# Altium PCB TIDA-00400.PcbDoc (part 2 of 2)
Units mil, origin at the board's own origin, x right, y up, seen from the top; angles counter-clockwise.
Board outline 2000 x 2000 mil, 2 copper layers (Top Layer, Bottom Layer), stack 62 mil thick; 123 components, 39 nets, 250 pads, 73 vias.
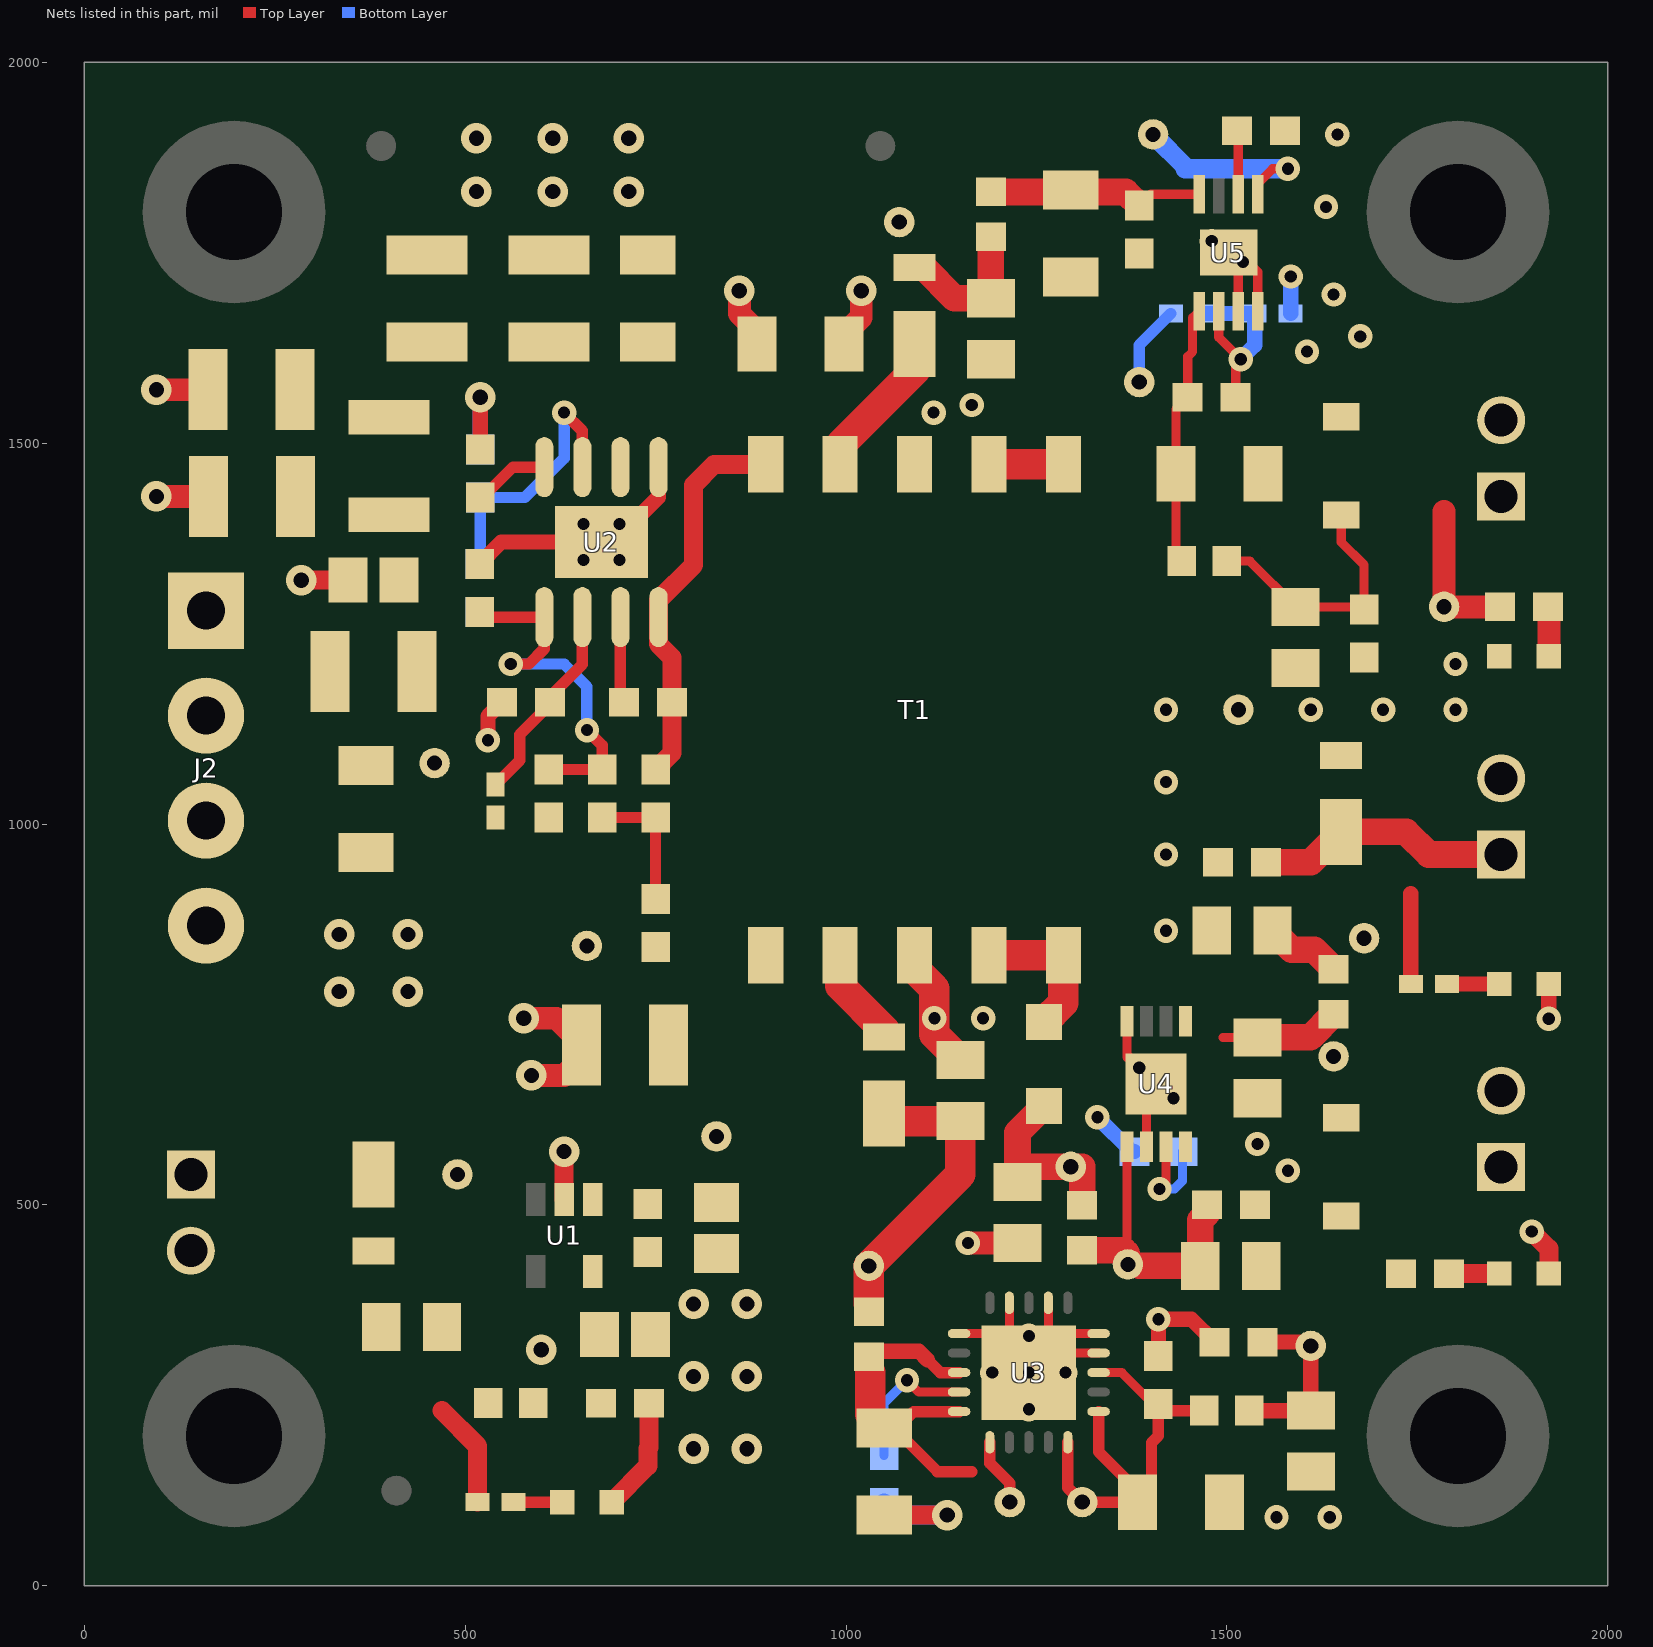
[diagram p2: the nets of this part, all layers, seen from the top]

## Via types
v1: diameter 32, hole 16, Top Layer to Bottom Layer, tented both sides, 48 vias
v2: diameter 40, hole 20, Top Layer to Bottom Layer, tented both sides, 25 vias

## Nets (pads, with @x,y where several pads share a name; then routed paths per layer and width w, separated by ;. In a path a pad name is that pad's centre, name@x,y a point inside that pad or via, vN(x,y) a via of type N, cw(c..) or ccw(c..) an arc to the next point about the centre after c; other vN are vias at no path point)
9.3V_NON_ISO: C8.1 C14.1 C15.2 C16.1 D2.2 R4.2 T1.10 TP5.1 TP6.1 U1.1
+3.3V_NON_ISO: C4.2 D1.1 J1.1 L2.2 R2.1 TP2.1 | length 139.2
  Top Layer w25: 470,230 516.38,183.62 R2.1@516.38,110
+5V_ISO: C30.1 C32.2 D9.1 J4.1 L8.2 R7.1 TP18.1 | length 556.9
  Top Layer w20: R7.1@1741.38,790 1741.38,908.62
  Top Layer w35: C32.2@1551.5,950 1610.2,950 D9.1@1650,989.8 1735.2,989.8 1765,960 J4.1@1860,960 ; C30.1@1560,860 1585,835 1614.53,835 L8.2@1640,809.53
+6V_ISO: C28.1 C29.2 L5.2 TP12.1 U4.5 U4.8 | length 387
  Top Layer w12: U4.5@1368.7,576.3 1368.7,436.3 TP12.1@1385,420
  Top Layer w35: L5.2@1310,440.47 1364.53,440.47 TP12.1@1368.7,436.3 ; TP12.1@1385,420 C28.1@1465,420 1465,480 1473.5,488.5 C29.2@1473.5,500
+15V_ISO: C31.2 C36.1 D8.1 J5.1 L7.2 R6.1 TP16.1 | length 225.2
  Top Layer w20: L7.2@1529.53,230 C36.1@1610,230 1610,305 1595,320 C31.2@1546.5,320
+18V_ISO: C18.1 L3.2 TP9.1 U3.13 U3.15 U3.16 | length 536.8
  Top Layer w15: C18.1@1050,207.09 C18.1@1062.91,207.09 ; 1106.97,296.77 1123.74,280 U3.13@1148.46,280 ; U3.15@1148.46,228.82 1088.82,228.82 1067.09,207.09 C18.1@1062.91,207.09 ; 1165,150 1120,150 C18.1@1062.91,207.09 ; U3.16@1188.82,188.46 1188.82,161.18 1215,135 TP9.1@1215,110
  Top Layer w20: L3.2@1030,300.47 1037.53,308 1095.74,308 1106.97,296.77
  Top Layer w40: 1032,280.7 1032,225.09 C18.1@1050,207.09
+24VDC: C2.1 C3.1 F1.1 L1.1 RV1.2 TP1.1
-15V_ISO: C35.2 C37.2 D7.2 J3.1 L6.2 R8.1 TP19.1 | length 536.8
  Top Layer w12: L6.2@1499.53,1345 1530,1345 C35.2@1590,1285 C37.2@1676.5,1285 ; D7.2@1650,1405.53 1650,1370 1680,1340 C37.2@1680,1281.5
  Top Layer w30: 1785,1410 TP19.1@1785,1285 R8.1@1858.5,1285
-18V_ISO: C22.1 C24.2 L4.2 TP14.1 U5.5 U5.8 | length 547.5
  Top Layer w12: C24.2@1385,1811.5 1400.1,1826.6 U5.8@1463.6,1826.6 ; U5.5@1540.4,1826.6 1540.4,1840.4 1560,1860 v1(1580,1860)
  Top Layer w35: L4.2@1190,1829.53 1366.97,1829.53 C24.2@1385,1811.5
  Bottom Layer w25: TP14.1@1403,1905 1448,1860 ; 1445,1860 1448,1860 ; v1(1580,1860) 1448,1860
GND: C1.2 C2.2 C3.2 C4.1 C5.1 C6.2 C7.1 C8.2 C9.2 C10.2 C13.1 C14.2 C16.2 C17.1 D1.2 D3.1 J1.2 J2.3 J2.4 R1.1 R12.1 RV1.1 U1.2 U2.1 U2.9 | length 998.9
  Top Layer w20: R1.1@518.98,1341.5 547.48,1370 U2.9@678.98,1370 695,1370 753.98,1428.98 U2.1@753.98,1468.43 ; v1(530,1110) 530,1141.5 C6.2@548.5,1160
  Top Layer w25: v2(285,1320) C3.2@346.54,1320 ; U1.2@630,507.24 v2(630,570) ; D3.1@692.48,110 740,157.52 740,180 ; 741.5,181.5 C10.2@741.5,240
  Top Layer w30: v2(95,1430) C2.2@163.23,1430 ; v2(95,1570) C1.2@162.91,1570 ; v2(577.09,745) 620,745 C8.2@640,725 ; v2(587.09,670) 630,670 C8.2@650,690 ; v2(860,1700) 860,1670 882.91,1647.09 C17.1@882.91,1630
  other v1: 655.35,1346.38 702.6,1346.38 655.35,1393.62 702.6,1393.62
  other v2: 800,180 870,180 800,275 870,275 800,370 870,370 335,780 425,780 335,855 425,855 515,1830 615,1830 715,1830 515,1900 615,1900 715,1900
NetC1_1: C1.1 C5.2 C7.2 C13.2 L1.2 R3.2 R11.2 TP3.1 U2.2 | length 117
  Top Layer w20: R3.2@520,1491.49 TP3.1@520,1550
  Bottom Layer w20: R11.2@520,1491.5 TP3.1@520,1550
NetC6_1: C6.1 D2.1 U2.6 | length 260.1
  Top Layer w15: D2.1@540,1051.65 571.8,1083.45 571.8,1117.33 611.5,1157.03 C6.1@611.5,1160 ; C6.1@611.5,1167.03 653.98,1209.51 U2.6@653.98,1271.57
NetC9_1: C9.1 C10.1 L2.1 TP4.1 U1.5
NetC11_1: C11.1 C15.1 R5.1 | length 177
  Top Layer w15: C11.1@680,1008.5 R5.1@750,1008.5 C15.1@750,901.5
NetC11_2: C11.2 R1.2 R4.1 U2.5 | length 480.9
  Top Layer w15: R1.2@518.98,1278.5 525.91,1271.57 U2.5@603.98,1271.57 603.98,1230 583.98,1210 v1(560,1210) ; R4.1@610,1071.5 C11.2@680,1071.5 680,1103.18 v1(660,1123.18)
  Bottom Layer w15: v1(560,1210) 630,1210 660,1180 v1(660,1123.18)
NetC12_1: C12.1 U2.7 | length 103.8
  Top Layer w15: C12.1@698.5,1170 703.98,1175.47 U2.7@703.98,1271.57
NetC12_2: C12.2 R5.2 T1.1 U2.8 | length 514.7
  Top Layer w25: R5.2@750,1071.5 771.5,1092.99 C12.2@771.5,1160 771.5,1218.5 753.98,1236.02 U2.8@753.98,1271.57 753.98,1293.98 800,1340 800,1445 827.05,1472.05 T1.1@894.72,1472.05
NetC19_1: C19.1 D4.1 L3.1 TP7.1 | length 393.8
  Top Layer w40: L3.1@1030,370 TP7.1@1030,420 1150,540 C19.1@1150,610 1059.8,610 D4.1@1050,619.8
NetC20_2: C20.2 D5.2 L4.1 TP8.1 | length 197.1
  Top Layer w35: D5.2@1090,1730.2 1102.19,1730.2 1142.39,1690 C20.2@1190,1690 L4.1@1190,1770.47
NetC21_1: C21.1 D6.1 L5.1 TP10.1 | length 258.1
  Top Layer w35: D6.1@1260,629.88 1225,594.88 C21.1@1225,530 1245,550 1310,550 L5.1@1310,499.53
NetC23_1: C23.1 C25.2 L7.1 TP11.1 U3.1 U3.3 U3.20 | length 598.6
  Top Layer w12: U3.3@1331.54,280 1362,280 1403.5,238.5 C25.2@1410,238.5
  Top Layer w15: U3.20@1291.18,188.46 1291.18,128.82 TP11.1@1310,110 C23.1@1382.91,110 ; U3.1@1331.54,228.82 1331.54,176.1 1382.91,124.72 C23.1@1382.91,110 ; L7.1@1470.47,230 1418.5,230 C25.2@1410,238.5 1410,197 1401,188 1401,128.09 C23.1@1382.91,110
NetC26_1: C26.1 C27.1 L6.1 R10.1 TP13.1 U5.1 | length 451
  Top Layer w12: L6.1@1440.47,1345 1432.91,1352.56 C26.1@1432.91,1460 1432.91,1544.41 C27.1@1448.5,1560 1448.5,1613.5 1455,1620 1455,1664.4 U5.1@1463.6,1673
  Bottom Layer w15: TP13.1@1385,1580 1385,1628.62 R10.1@1426.38,1670
NetC27_2: C27.2 R9.1 R10.2 U5.2 | length 258
  Top Layer w12: U5.2@1489.2,1673 1489.2,1638.79 v1(1517.99,1610) 1511.49,1603.51 C27.2@1511.49,1560
  Bottom Layer w20: R10.2@1473.62,1670 R9.1@1536.38,1670 1536.38,1628.39 v1(1517.99,1610)
NetC33_1: C33.1 U5.6 | length 80.1
  Top Layer w12: U5.6@1514.8,1826.6 C33.1@1514.8,1906.69
NetC34_1: C34.1 L8.1 TP17.1 U4.1 | length 157.6
  Top Layer w12: 1495,720 C34.1@1540,720
  Top Layer w35: C34.1@1540,720 1609.53,720 L8.1@1640,750.47
NetC38_1: C38.1 U4.7 | length 131.6
  Top Layer w12: v1(1411.52,521) 1419.9,529.38 U4.7@1419.9,576.3
  Bottom Layer w12: v1(1411.52,521) 1431,521 1441.5,531.5 C38.1@1441.5,570
NetC39_1: C39.1 U3.14 | length 185.9
  Top Layer w12: v1(1080,270) 1095.59,254.41 U3.14@1148.46,254.41
  Bottom Layer w12: C39.1@1050,171.5 1050,240 v1(1080,270)
NetD3_2: D3.2 R2.2 | length 63.9
  Top Layer w15: R2.2@563.62,110 D3.2@627.52,110
NetD4_2: D4.2 T1.9 | length 121.8
  Top Layer w40: T1.9@992.36,827.95 992.36,787.64 D4.2@1050,730
NetD5_1: D5.1 T1.2 | length 198.2
  Top Layer w40: T1.2@992.36,1472.05 992.36,1497.36 1090,1595 D5.1@1090,1629.8
NetD6_2: D6.2 T1.6 T1.7 | length 195.9
  Top Layer w40: T1.7@1187.64,827.95 T1.6@1285.28,827.95 1285.28,765.39 D6.2@1260,740.12
NetD10_1: D10.1 R8.2 | length 64
  Top Layer w30: D10.1@1922.48,1220 R8.2@1922.48,1284.02
NetD11_2: D11.2 R7.2 | length 68.9
  Top Layer w20: R7.2@1788.62,790 D11.2@1857.52,790
NetD12_2: D12.2 R6.2 | length 66
  Top Layer w25: R6.2@1791.5,410 D12.2@1857.52,410
NetF1_2: F1.2 J2.1 J2.2
NetR3_1: R3.1 U2.4 | length 100.5
  Top Layer w15: R3.1@520,1428.5 522.97,1428.5 562.89,1468.43 U2.4@603.98,1468.43
NetR11_1: R11.1 R12.2 U2.3 | length 358.8
  Top Layer w15: v1(630,1540) 653.98,1516.02 U2.3@653.98,1468.43
  Bottom Layer w15: R12.2@520,1342.52 R11.1@520,1428.5 578.5,1428.5 630,1480 v1(630,1540)
NetT1_4: T1.4 T1.5 | length 97.6
  Top Layer w40: T1.4@1187.64,1472.05 T1.5@1285.28,1472.05
SGND: C17.2 C18.2 C19.2 C20.1 C21.2 C22.2 C23.2 C24.1 C25.1 C26.2 C28.2 C29.1 C30.2 C31.1 C32.1 C33.2 C34.2 C35.1 C36.2 C37.1 C38.2 C39.2 D7.1 D8.2 D9.2 D10.2 D11.1 D12.1 J3.2 J4.2 J5.2 R9.2 T1.3 T1.8 TP15.1 U3.4 U3.5 U3.7 U3.9 U3.11 U3.21 U4.4 U4.6 U4.9 U5.3 U5.4 U5.9 | length 1470
  Top Layer w12: U3.11@1148.46,331.18 U3.21@1188.82,331.18 ; U3.21@1214.41,305.59 U3.9@1214.41,371.54 ; U3.7@1265.59,371.54 1265.59,305.59 U3.4@1331.54,305.59 ; U3.21@1291.18,331.18 U3.5@1331.54,331.18 ; U4.9@1368.8,693.8 U4.4@1368.8,741.3 ; U4.9@1370.5,695.5 U4.9@1407,659 1394.3,646.3 U4.6@1394.3,576.3 ; U5.9@1502.4,1750 U5.9@1514.8,1737.6 ; U5.3@1514.8,1673 U5.9@1514.8,1737.6 ; U5.4@1540.4,1673 1540.4,1724.6 1527.4,1737.6 U5.9@1514.8,1737.6
  Top Layer w20: C25.1@1410,301.5 v1(1410,350) 1453.5,350 C31.1@1483.5,320 ; v1(1922.48,744.48) D11.1@1922.48,790
  Top Layer w25: C18.2@1050,92.91 v2(1132.91,92.91) ; v1(1900,465) 1922.48,442.52 D12.1@1922.48,410
  Top Layer w30: C17.2@997.09,1630 997.09,1642.09 1020,1665 v2(1020,1700) ; v1(1160,450) C21.2@1225,450
  Top Layer w40: T1.8@1090,827.95 1090,810 1116,784 1116,724 C19.2@1150,690
  Bottom Layer w20: v1(1330,615) 1375,570 C38.2@1378.5,570 ; R9.2@1583.62,1670 v1(1583.62,1718.62)
  Bottom Layer w25: C39.2@1050,108.5 1065.59,92.91 v2(1132.91,92.91)
  other v1: 1565,90 1635,90 1240,231.84 1191.84,280 1240,280 1288.16,280 1240,328.16 1580,545 1540,580 1430,640 1385,680 1116,745 1180,745 1420,860 1420,960 1420,1055 1420,1150 1610,1150 1705,1150 1800,1150 1800,1210 1115,1540 1165,1550 1605,1620 1675,1640 1640,1695 1521.1,1737.6 1480,1765 1630,1810 1645,1905
pads on no net: FID1.1 FID2.1 FID3.1 FID4.1 FID5.1 FID6.1 H1.1 H2.1 H3.1 H4.1 U1.3 U1.4 U3.2 U3.6 U3.8 U3.10 U3.12 U3.17 U3.18 U3.19 U4.2 U4.3 U5.7

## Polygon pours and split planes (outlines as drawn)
SGND on Top Layer "Top Layer-No Net" (solid, remove dead copper, pour order 39): 1560,175 1645,175 1660,160 1660,80 1640,60 1555,60 1455,65 1445,75 1445,135 1475,165 1550,165
SGND on Top Layer "Top Layer-No Net" (solid, remove dead copper, pour order 45): 1570,1420 1500,1420 1495,1425 1495,1505 1505,1515 1560,1515 1580,1535 1580,1645 1570,1655 1515,1655 1510,1660 1510,1720 1505,1725 1390,1725 1325,1660 1325,1600 1310,1585 1160,1585 1160,1635 1250,1635 1260,1645 1260,1750 1275,1765 1435,1765 1450,1780 1580,1780 1610,1810 1610,1880 1600,1890 1560,1890 1555,1895 1555,1925 1560,1930 1695,1930 1700,1925 1700,1550
+15V_ISO on Top Layer "Top Layer-No Net" (solid, remove dead copper, pour order 43): 1515,255 1515,215 1525,205 1625,205 1650,230 1650,325 1690,365 1725,365 1735,375 1735,455 1755,475 1835,475 1865,505 1915,505 1930,520 1930,580 1920,590 1770,590 1710,530 1630,530 1600,500 1600,355 1585,340 1545,340 1535,330 1535,275
SGND on Top Layer "Top Layer-No Net" (solid, remove dead copper, pour order 35): 1570,385 1520,385 1520,605 1505,620 1355,620 1335,640 1335,750 1375,750 1375,700 1380,695 1450,695 1480,665 1570,665 1600,635 1680,635 1685,630 1685,605 1680,600 1610,600 1600,590 1600,540 1575,515 1575,390
NetC34_1 on Top Layer "Top Layer-No Net" (solid, remove dead copper, pour order 51): 1440,725 1475,725 1510,690 1600,690 1625,665 1670,665 1680,675 1680,765 1675,770 1440,770
-18V_ISO on Top Layer "Top Layer-No Net" (solid, remove dead copper, pour order 48): 1465,1810 1440,1810 1425,1795 1260,1795 1240,1815 1125,1815 1120,1820 1120,1885 1125,1890 1345,1890 1390,1935 1440,1935 1450,1925 1450,1865 1465,1850
9.3V_NON_ISO on Top Layer "Top Layer-No Net" (solid, remove dead copper, pour order 40): 640,480 880,480 890,490 890,760 910,780 910,860 690,860 640,910 640,1020 520,1020 500,1000 500,810 520,790 720,790 740,770 740,570 720,550 640,550
NetC9_1 on Top Layer "Top Layer-No Net" (solid, remove dead copper, pour order 44): 580,190 590,180 680,180 690,190 690,440 650,440 640,430 640.12,360 620,340 590,340 580,330
+24VDC on Top Layer "Top Layer-No Net" (solid, remove dead copper, pour order 34): 410,1140 380,1110 350,1110 340,1100 340,1050 350,1040 480,1040 490,1050 490,1210 470,1230 470,1420 460,1430 330,1430 310,1450 310,1480 300,1490 250,1490 250,1380 410,1380
NetF1_2 on Top Layer "Top Layer-No Net" (solid, remove dead copper, pour order 32): 340,1150 340,1250 290,1250 200,1340 90,1340 80,1330 80,1120 110,1090 210,1090 270,1150
NetC23_1 on Top Layer "Top Layer-No Net" (solid, remove dead copper, pour order 41): 1395,55 1410,70 1410,155 1450,195 1480,195 1485,200 1485,255 1380,255 1380,230 1365,215 1320,215 1320,195 1280,195 1280,75 1300,55
-15V_ISO on Top Layer "Top Layer-No Net" (solid, remove dead copper, pour order 50): 1495,1385 1610,1385 1620,1395 1620,1430 1660,1470 1910,1470 1910,1380 1905,1375 1720,1375 1710,1365 1710,1280 1705,1275 1495,1275 1485,1285 1485,1375
+18V_ISO on Top Layer "Top Layer-No Net" (solid, remove dead copper, pour order 37): 1200,140 1130,140 1090,180 1000,180 990,190 990,300 1000,310 1100,310 1116.52,292.75 1110,230 1140,230 1140,200 1150,190 1195,190 1195,145 1200,145
NetC20_2 on Top Layer "Top Layer-No Net" (solid, remove dead copper, pour order 52): 1230,1680 1135,1680 1100,1715 1030,1715 1020,1725 1020,1805 1035,1820 1080,1820 1120,1780 1225,1780 1230,1775 1230,1690
NetC26_1 on Top Layer "Top Layer-No Net" (solid, remove dead copper, pour order 49): 1460,1695 1460,1300 1450,1290 1390,1290 1375,1305 1375,1535 1345,1565 1345,1650 1390,1695
+5V_ISO on Top Layer "Top Layer-No Net" (solid, remove dead copper, pour order 47): 1685,795 1555,795 1540,810 1540,995 1575,1030 1730,1030 1765,995 1920,995 1930,985 1930,885 1925,880 1715,880 1705,870 1705,815
+6V_ISO on Top Layer "Top Layer-No Net" (solid, remove dead copper, pour order 53): 1280,460 1420,460 1460,500 1460,550 1450,560 1450,590 1480,590 1490,580 1490,400 1485,395 1360,395 1335,420 1280,420 1275,425 1275,455
NetC21_1 on Top Layer "Top Layer-No Net" (solid, remove dead copper, pour order 54): 1304,481 1275,510 1195,510 1195,540 1210,555 1210,630 1235,655 1290,655 1300,645 1300,605 1335,570 1335,481
NetC19_1 on Top Layer "Top Layer-No Net" (solid, remove dead copper, pour order 55): 1100,350 995,350 990,355 990,615 1010,635 1165,635 1165,545 1110,490 1110,360
GND on Top Layer "Top Layer-No Net" (solid, remove dead copper, pour order 56): 240,1055 310,985 455,985 470,970 470,755 450,735 95,735 80,750 80,1035 100,1055
GND on Top Layer "Top Layer-No Net" (solid, remove dead copper, pour order 57): 415,450 395,470 95,470 80,455 80,370 90,360 310,360 345,325 345,285 355,275 410,275 415,280
GND on Top Layer "Top Layer-No Net" (solid, remove dead copper, pour order 58): 880,450 895,435 895,85 880,70 700,70 685,85 685,120 730,165 730,400 720,410.02 720,440 730,450
+3.3V_NON_ISO on Top Layer "Top Layer-No Net" (solid, remove dead copper, pour order 46): 540,670 520,690 110,690 80,660 80,510 90,500 430,500 440,490 440,190 450,180 540,180
GND on Top Layer "Top Layer-No Net" (solid, remove dead copper, pour order 59): 895,1780 865,1750 815,1750 790,1725 375,1725 350,1750 350,1915 365,1930 875,1930 895,1910
GND on Top Layer "Top Layer-No Net" (solid, remove dead copper, pour order 61): 190,1375 90,1375 70,1395 70.26,1395.26 70.26,1572.69 70.26,1640.26 85,1655 180,1655 185,1655 195,1645 195,1380 190,1375
SGND on Top Layer "Top Layer-No Net" (solid, remove dead copper, pour order 42): 1505,825 1410,825 1390,845 1390,1185 1435,1230 1795,1230 1805,1240 1875,1240 1875,1185 1910,1150 1910,1040 1890,1020 1795,1020 1740,1075 1520,1075 1505,1060
NetC1_1 on Top Layer "Top Layer-No Net" (solid, remove dead copper, pour order 36): 250,1510 230,1530 230,1630 260,1660 770,1660 790,1640 790,1590 770,1570 740,1570 720,1550 720,1430 690,1430 690,1550 650,1590 570,1590 540,1560 540,1490 500,1490 500,1545 450,1545 450,1510
SGND on Top Layer "Top Layer-No Net" (solid, remove dead copper, pour order 33): 1210,670 1110,670 1095,685 1095,775 1085,785 1065,785 1065,865 1115,865 1120,860 1120,800 1130,790 1130,765 1135,760 1200,760 1210,750
SGND on Top Layer "Top Layer-No Net" (solid, remove dead copper, pour order 38): 1180,1570 1190,1560 1190,1540 1185,1535 1135,1535 1110,1500 1110,1440 1070,1440 1070,1510 1120,1560 1145,1560 1155,1570
SGND on Bottom Layer "Top Layer-No Net" (solid, remove dead copper, pour order 62): 985,50 1925,50 1950,75 1950,1915 1920,1945 1005,1945 995,1935 995,1445 1000,1440 1350,1440 1365,1425 1365,880 1350,865 980,865 975,860 975,765 985,755
GND on Bottom Layer "Top Layer-No Net" (solid, remove dead copper, pour order 60): 895,50 700,50 85,50 55,80 55,410 55,1900 85,1930 105,1950 330,1950 875,1950 895,1930 895,1655 895,1565 830,1500 820,1490 820,1435 820,860 835,845 910,845 915,840 915,820 915,775 895,755 895,705 895,50

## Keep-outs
Keep-Out Layer:
  pour cut-out: 980,0 980,750 970,760 970,1500 990,1520 990,1990 900,1990 900,1530 920,1510 920,770 900,750 900,0
  lines w4: 35,35 35,1965 1965,1965 1965,35 35,35
  text ".Layer_Name" at 77,-1358.49 h60

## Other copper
Top Layer:
  region net NetC34_1: 1480,770 1445,770 1440,765 1440,725 1480,725
  region net SGND: 1350,735 1350,680 1365,680 1365,735
  region net SGND: 1514.8,1737.6 1514.8,1665.2 1515,1665 1535,1665 1535,1730 1527.4,1737.6
  text ".Layer_Name" at 77,-1358.49 h60
Bottom Layer:
  text ".Layer_Name" at 77,-1358.49 h60

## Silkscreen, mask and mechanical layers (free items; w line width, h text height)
Top Overlay:
  circle w10: c1364,228 r5
  circle w10: c670,550 r10
  circle w10: c793.79,1470 r12.21
  lines w6: 553,1560 567,1574 611,1574 ; 582.65,1303 582.65,1424.35 ; 1109,416 1170,416 1161,425 1161,406 1170,415 ; 1330.6,592 1330.6,541.2 1406.8,541.2 1480.6,541.2 1480.6,776.2 1330.6,776.2 1330.6,644.4 ; 1429,1650 1429,1857 ; 1573.6,1633 1573.6,1695 ; 1573.6,1743.4 1573.6,1836 ; 1583.29,345.36 1592.57,354.64
  text ".Layer_Name" at 77,-1358.49 h60
Bottom Overlay:
  rectangle: 385,1595.5 685,1695.5
  text ".PCB_Rev" at 365,1610 h60
  text ".PRJ_Number" at 1351,1605.5 h60
  text "-" at 750,1595 h60
  text ".Layer_Name" at 77,-1358.49 h60
Top Paste:
  text ".Layer_Name" at 77,-1358.49 h60
Bottom Paste:
  text ".Layer_Name" at 77,-1358.49 h60
Top Solder:
  text ".Layer_Name" at 77,-1358.49 h60
  text ".Layer_Name" at 77,-1358.49 h60
Bottom Solder:
  text ".Layer_Name" at 77,-1358.49 h60
Drill Guide:
  text ".Layer_Name" at 77,-1358.49 h60
M1 Board Outline:
  the board outline again, w10
  text ".Layer_Name" at 77,-1358.49 h60
M2 Board Dimensions:
  rectangle: -500.5,-785.5 -375.5,-660.5
  rectangle: -375.5,-910.5 -0.5,-785.5
  lines w7: -500.5,-785.5 499.5,-785.5 ; -375.5,-910.5 -375.5,-660.5 ; -250.5,-910.5 -250.5,-660.5 ; -0.5,-910.5 -0.5,-660.5 ; 249.5,-910.5 249.5,-660.5 ; -500.5,-910.5 499.5,-910.5 499.5,-660.5 -500.5,-660.5 -500.5,-910.5
  lines w10: -500.5,-975.5 -500.5,-955.5 ; -440.5,-985.5 -500.5,-965.5 ; -440.5,-945.5 -500.5,-965.5 ; -276.42,-965.5 -500.5,-965.5 ; 275.42,-965.5 499.5,-965.5 ; 439.5,-985.5 499.5,-965.5 ; 439.5,-945.5 499.5,-965.5 ; 499.5,-975.5 499.5,-955.5
  text "1000 (mil)" at -266.42,-1001.49 h60
  text ".Layer_Name" at 77,-1358.49 h60
M3 3D STEP Top:
  text ".Layer_Name" at 77,-1358.49 h60
M4 3D STEP Bottom:
  text ".Layer_Name" at 77,-1358.49 h60
M5 Assembly Top:
  circle w6: c667,475 r8
  circle w10: c160,1280 r25.5
  lines w3.94: 1920,440 1920,470
  lines w4: 1865,1180 1885,1180 ; 1875,830 1890,830 ; 1900,1165 1900,1195 ; 1905,815 1905,845 ; 1915,1180 1900,1180 ; 1920,830 1905,830 ; 1900,1180 1885,1195 1885,1165 1900,1180 ; 1905,830 1890,815 1890,845 1905,830
  lines w6: 717,109 742,109 ; 743,134 743,84 768,109 ; 768,83 768,133 ; 789,109 768,109 ; 744,133 744,133 ; 744,133 768,109
  lines w10: -792,-1430.17 5808,-1430.17 ; -792,-1226.83 5810,-1226.83 ; -792,-1023.5 -792,-1633.5 3213,-1633.5 5810,-1633.5 5810,-1023.5 -791.5,-1023.5 -791.5,-1633.5 784,-1633.5 ; 1673,-1633.5 1673,-1023.5 ; 2940,-1226.83 2940,-1023.5 ; 3780,-1226.83 3780,-1023.5 ; 4402,-1640 4402,-1437.17
  text "11" at 1100,330 h26
  text "COMPONENTS MARKED 'DNP' SHOULD NOT BE POPULATED." at 653.5,-818.5 h60
  text "ASSEMBLY VARIANT:" at 653,-934 h60
  text ".VariantName" at 1689,-934 h60
  text "PCB VIEWED FROM TOP SIDE" at -728.5,-1155.67 h60
  text "BOARD #:" at 1748,-1155.67 h60
  text ".PRJ_Number" at 2293.5,-1155.67 h60
  text "REV:" at 3138,-1155.67 h60
  text ".PCB_Rev" at 3429.5,-1155.67 h60
  text "SVN REV:" at 3976,-1155.67 h60
  text ".VersionControl_RevNumber" at 4482,-1155.67 h60
  text "IGNORE ->" at -728.5,-1358.49 h60
  text "PLOT NAME =" at -728.5,-1564.34 h60
  text ".plot_File_Name" at 77,-1564.34 h60
  text "GENERATED    :" at 1750,-1564.34 h60
  text ".Print_Date" at 2619.5,-1564.34 h60
  text ".Print_Time" at 3348.5,-1564.34 h60
  text "TEXAS INSTRUMENTS" at 4613,-1564.34 h60
M6 Assembly Bottom:
  lines w10: -792.5,-1227.33 5809.5,-1227.33 ; -790.5,-1430.67 5809.5,-1430.67 ; 615.5,-1640.5 615.5,-1437.67 ; 1237.5,-1227.33 1237.5,-1024 ; 2077.5,-1227.33 2077.5,-1024 ; 3344.5,-1634 3344.5,-1024 ; 4233.5,-1634 5809,-1634 5809,-1024 -792.5,-1024 -792.5,-1634 1804.5,-1634 5809.5,-1634 5809.5,-1024
  text "COMPONENTS MARKED 'DNP' SHOULD NOT BE POPULATED." at 5602,-818 h60
  text ".VariantName" at 4558,-934 h60
  text "ASSEMBLY VARIANT:" at 5597,-934 h60
  text ".VersionControl_RevNumber" at 535.5,-1156.17 h60
  text "SVN REV:" at 1041.5,-1156.17 h60
  text ".PCB_Rev" at 1588,-1156.17 h60
  text "REV:" at 1879.5,-1156.17 h60
  text ".PRJ_Number" at 2724,-1156.17 h60
  text "BOARD #:" at 3269.5,-1156.17 h60
  text "PCB VIEWED FROM BOTTOM SIDE" at 5746,-1156.17 h60
  text "IGNORE ->" at 2047.85,-1358.49 h60
  text "TEXAS INSTRUMENTS" at 404.5,-1564.84 h60
  text ".Print_Time" at 1669,-1564.84 h60
  text ".Print_Date" at 2398,-1564.84 h60
  text "GENERATED    :" at 3267.5,-1564.84 h60
  text ".plot_File_Name" at 4940.5,-1564.84 h60
  text "PLOT NAME =" at 5746,-1564.84 h60
M9 Title Sheet:
  drawing of 57 lines, arcs and shapes, not listed
  text "1" at 239.84,7536.5 h70
  text "2" at 2735.5,7536.5 h70
  text "3" at 5224.84,7536.5 h70
  text "4" at 7731.51,7536.5 h70
  text "5" at 10230.5,7536.5 h70
  text "6" at 12735.5,7536.5 h70
  text "A" at -916.5,6393.5 h70
  text "A" at 13883.5,6393.5 h70
  text "B" at -916.5,4013.5 h70
  text "B" at 13883.5,4013.5 h70
  text "C" at -916.5,1638.5 h70
  text "C" at 13883.5,1638.5 h70
  text "PROJECT TITLE:" at 10843.5,-222.5 h45
  text ".PRJ_Title" at 10893.5,-355.83 h70
  text "DESIGNED FOR:" at 10843.5,-523.5 h45
  text ".PRJ_Customer" at 10893.5,-663.5 h70
  text "D" at -916.5,-731.5 h70
  text "D" at 13883.5,-731.5 h70
  text "FILE NAME:" at 10843.5,-823.5 h45
  text ".PCB_File_Name_No_Path" at 10893.5,-943.5 h70
  text "Texas Instruments (TI) and/or its licensors do not warrant the accuracy or completeness of this specification" at 5874,-1105.34 h45
  text "ENGINEER:" at 10843.5,-1113.5 h45
  text "LAYOUT BY:" at 12348.5,-1113.5 h45
  text "or any information contained therein. TI and/or its licensors do not warrant that this design will meet" at 5829.01,-1218 h45
  text ".PRJ_Engineer" at 10893.5,-1268.49 h70
  text ".PCB_Layout" at 12399,-1268.49 h70
  text "the specifications, will be suitable for your application or fit for any particular purpose, or will operate in" at 5829.01,-1330.67 h45
  text "ALTIUM DESIGNER VERSION:" at 12348.5,-1423.5 h45
  text "an implementation. TI and/or its licensors do not warrant that the design is production worthy. You should" at 5829.01,-1443.33 h45
  text "completely validate and test your design implementation to confirm the system functionality for your application." at 5874,-1556 h45
  text ".print_Scale" at 10893.5,-1556.83 h70
  text ".Application_BuildNumber" at 12399,-1556.83 h70
  text "1" at 239.84,-1763.5 h70
  text "2" at 2735.5,-1763.5 h70
  text "3" at 5224.84,-1763.5 h70
  text "4" at 7731.51,-1763.5 h70
  text "5" at 10230.5,-1763.5 h70
  text "6" at 12735.5,-1763.5 h70
M10 Fab Notes:
  drawing of 228 lines, arcs and shapes, not listed
  text "DESIGN INFORMATION" at 11881.02,6310 h60
  text "(REFER ALSO ARRAY/PANEL PROFILING INFORMATION)" at 11519.46,6148.29 h60
  text "BOARD SIZE" at 10833.46,6144 h60
  text "2000MIL" at 11295.78,6016.18 h60
  text "X" at 11801.46,6016.18 h60
  text "2000MIL" at 12032.78,6016.18 h60
  text "Number of Layers :" at 11236.46,5819 h60
  text "2" at 12331.27,5809 h60
  text "MIN. TRACK WIDTH:" at 11236.46,5680 h60
  text "12" at 12332.7,5680 h60
  text "MIL" at 12487.46,5680 h60
  text "8.6" at 12285,5550 h60
  text "MIN. CLEARANCE:" at 11236.46,5548 h60
  text "MIL" at 12487.46,5548 h60
  text "MIN. VIA PAD SIZE:" at 11236.46,5416 h60
  text "32" at 12302.71,5416 h60
  text "MIL" at 12487.46,5416 h60
  text "0.2032mm (8MIL)" at 11931.46,5274.29 h60
  text "MINIMUM ANNULAR RING" at 10907.23,5270 h60
  text "EXTERNAL" at 12685,5270 h60
  text "PER" at 11107.23,5152 h60
  text "IPC-D-275 CLASS 2 LEVEL C" at 11327.23,5152 h60
  text "MIL, HOLES" at 12815.46,5039.71 h60
  text "+/-" at 12423,5039 h60
  text "+/-" at 13277,5039 h60
  text "REGISTRATION TOLERANCES:" at 10907.23,5034 h60
  text "METAL" at 12107,5034 h60
  text "5" at 12683.2,5034 h60
  text "3" at 13516.2,5034 h60
  text "MIL" at 13632.46,5034 h60
  text "MATERIAL:" at 10832.46,4824.54 h60
  text "FR-4 High Tg" at 11818.9,4684.21 h60
  text "FR-4" at 13115,4684.21 h60
  text "FR-408" at 11253.46,4675.64 h60
  text "X" at 12554.46,4676 h60
  text "OTHER" at 12741.46,4675.64 h60
  text "63 MIL (1.6mm) +/-10%" at 11573.56,4512.92 h60
  text "THICKNESS:" at 10907.23,4508.64 h60
  text "X" at 11445.4,4508.64 h60
  text "OTHER" at 12858.46,4508.64 h60
  text "TOLERANCE:" at 10907.23,4350.64 h60
  text "X" at 11746.53,4350.64 h60
  text "ANSI IPC-6012 TYPE 3 CLASS 2" at 11933.48,4350.64 h60
  text "OTHER +/-" at 11933.46,4194.64 h60
  text "BOW & TWIST:" at 10907.23,4037.64 h60
  text "X" at 11746.53,4037.64 h60
  text "ANSI IPC-6012 TYPE 3 CLASS 2" at 11933.48,4037.64 h60
  text "OTHER +/-" at 11933.46,3879.13 h60
  text "COPPER THICKNESS (FINISHED):" at 10832.46,3743.64 h60
  text "1.4MIL (1oz)" at 11712.46,3590.92 h60
  text "2MIL (1.4oz)" at 12479.46,3590.92 h60
  text "2.8MIL (2oz)" at 13206.46,3590.92 h60
  text "OUTER:" at 11189.46,3586.64 h60
  text "X" at 11584,3586 h60
  text "1.4MIL (1oz)" at 11712.46,3433.92 h60
  text "2.8MIL (2oz)" at 12479.46,3433.92 h60
  text "N/A" at 13206,3434.29 h60
  text "INNER SIGNAL:" at 10900.38,3429.64 h60
  text "DRILLING:" at 10832.46,3290.64 h60
  text "REFERENCE:" at 10907.23,3173.64 h60
  text "X" at 11555.46,3173.64 h60
  text "AS SHOWN" at 11742.46,3173.64 h60
  text "X" at 12456.46,3173.64 h60
  text "NC_DRILL FILES" at 12593.46,3173.64 h60
  text "PTH MIN COPPER THICKNESS:" at 10907.23,3015.64 h60
  text "X" at 12257.46,3015.64 h60
  text "1MIL" at 12394.46,3015.64 h60
  text "OTHER" at 12891.46,3015.64 h60
  text "BOARD FINISH:" at 10832.46,2856.64 h60
  text "SILKSCREEN:" at 10987.68,2738.64 h60
  text "X" at 11936.46,2738.64 h60
  text "TOP" at 12062.46,2738.64 h60
  text "X" at 12446.46,2738.64 h60
  text "BOTTOM" at 12573.46,2738.64 h60
  text "SILKSCREEN COLOR:" at 10987.68,2571.64 h60
  text "X" at 11935.42,2571.64 h60
  text "WHITE" at 12062.46,2571.64 h60
  text "OTHER" at 12573.46,2571.64 h60
  text "SOLDER RESIST COLOR:" at 10987.68,2401.64 h60
  text "X" at 11555.42,2242.44 h60
  text "GREEN" at 11682.46,2242.44 h60
  text "BLUE" at 12273.46,2242.44 h60
  text "OTHER" at 12811.46,2242.44 h60
  text "IMMERSION GOLD (ENIG)" at 11893.46,2053.92 h60
  text "ENEPIG" at 13231,2050.64 h60
  text "SURFACE FINISH:" at 10832.46,2049.64 h60
  text "X" at 11706.51,2049.64 h60
  text "IMM. TIN/SILVER OR EQUIV" at 11162,1892.64 h60
  text "OTHER" at 12593.46,1892.64 h60
  text "ARRAY/PANEL:" at 10832.46,1713.64 h60
  text "CUT AND TRIM PER MECH LAYER 1" at 11893.46,1709.35 h60
  text "N.C. ROUTE" at 11893.46,1557.64 h60
  text "X" at 12572.46,1557.64 h60
  text "V. SCORE" at 12759.46,1557.64 h60
  text "CERTIFICATION:" at 10832.46,1420.64 h60
  text "MATERIALS AND WORKMANSHIP FOR ALL PCBS" at 11557.46,1420.64 h60
  text "TO MEET OR EXCEED THE REQUIREMENTS OF:" at 11557.46,1322.64 h60
  text "X" at 11183.96,1186.13 h60
  text "ANSI IPC-A-600F CLASS ->" at 11322.96,1186.13 h60
  text "X" at 12962.02,1186.13 h60
  text "2" at 13080.96,1186.14 h60
  text "1" at 12765.96,1184.64 h60
  text "3" at 13434.96,1184.64 h60
  text "X" at 11186.02,1026.64 h60
  text "UL 94V-0" at 11322.96,1026.64 h60
  text "X" at 11998.02,1026.64 h60
  text "RoHS" at 12134.96,1026.64 h60
  text "OTHER" at 12779.36,1026.64 h60
  text "PER ORDER" at 13176.42,1026.64 h60
  text "ADDITIONAL REQUIREMENTS:" at 10832.46,885.64 h60
  text "VIA TENTING:" at 12050,885 h60
  text "X" at 12816.29,885.11 h60
  text "YES" at 12599.67,875.92 h60
  text "NO" at 12964.47,870.69 h60
  text "MICROSECTION:" at 10907.23,770.64 h60
  text "YES" at 11812.96,770.64 h60
  text "IMPEDANCE CONTROL:" at 12076,761 h60
  text "YES" at 13060,760 h60
  text "X" at 13602,753 h60
  text "NO" at 13435.47,742.69 h60
  text "REQUIRED" at 12674.46,614.49 h60
  text "BARE BOARD ELEC. TEST:" at 10907.23,611.64 h60
  text "NONE" at 12212.96,611.64 h60
  text "X" at 12547.46,611.64 h60
  text "PER ORDER" at 13266.46,611.64 h60
  text "MANUFACTURER'S UL:" at 10907.23,454.64 h60
  text "RAIL" at 12072.96,450.35 h60
  text "METAL" at 12564.77,450.35 h60
  text "X" at 12940,450 h60
  text "SILK" at 13076.46,450.35 h60
M11 Gerber Information:
  lines w10: -792,-1430.17 5808,-1430.17 ; -792,-1226.83 5810,-1226.83 ; -792,-1023.5 -792,-1633.5 3213,-1633.5 5810,-1633.5 5810,-1023.5 -791.5,-1023.5 -791.5,-1633.5 784,-1633.5 ; 1673,-1633.5 1673,-1023.5 ; 2940,-1226.83 2940,-1023.5 ; 3780,-1226.83 3780,-1023.5 ; 4402,-1640 4402,-1437.17
  text "REV:" at 3055,-1150 h60
  text "ALL ARTWORK VIEWED FROM TOP SIDE" at -728.5,-1155.67 h60
  text "BOARD #:" at 1748,-1155.67 h60
  text ".PRJ_Number" at 2293.5,-1155.67 h60
  text ".PCB_Rev" at 3429.5,-1155.67 h60
  text "SVN REV:" at 3976,-1155.67 h60
  text ".VersionControl_RevNumber" at 4482,-1155.67 h60
  text "LAYER NAME =" at -728.5,-1358.49 h60
  text "PLOT NAME =" at -728.5,-1564.34 h60
  text ".plot_File_Name" at 77,-1564.34 h60
  text "GENERATED    :" at 1750,-1564.34 h60
  text ".Print_Date" at 2619.5,-1564.34 h60
  text ".Print_Time" at 3348.5,-1564.34 h60
  text "TEXAS INSTRUMENTS" at 4613,-1564.34 h60
M12 Stackup:
  lines w7: 10900,7073.5 13665,7073.5 ; 10900,7199.4 13665,7199.4 ; 10840,6491 ccw(c10881,6491) 10881,6450 13684,6450 ccw(c13684,6491) 13725,6491 13725,7339 ccw(c13684,7339) 13684,7380 10881,7380 ccw(c10881,7339) 10840,7339 10840,6491
  text "Layer Stack Up Detail for: TIDA-00400.PcbDoc" at 10900,7244.4 h61
  text "Layer" at 10900,7152.4 h29
  text "Gerber" at 11876.44,7152.4 h29
  text "Copper" at 12453.74,7152.4 h29
  text "Dielectric" at 13078.4,7152.4 h29
  text "Name" at 10900,7094.4 h29
  text "Document" at 11876.44,7094.4 h29
  text "Thickness" at 12453.74,7094.4 h29
  text "Material" at 13078.4,7094.4 h29
  text "Top Solder Mask" at 10900,6982.81 h41
  text "(.GTS)" at 11876.44,6982.81 h41
  text "Solder Resist" at 13078.4,6982.81 h41
  text "Top Layer" at 10900,6866.56 h41
  text "(.GTL)" at 11876.44,6866.56 h41
  text "1.4mil" at 12453.74,6866.56 h41
  text "FR-4" at 13078.4,6808.44 h41
  text "Bottom Layer" at 10900,6750.31 h41
  text "(.GBL)" at 11876.44,6750.31 h41
  text "1.4mil" at 12453.74,6750.31 h41
  text "Bottom Solder Mask" at 10900,6634.06 h41
  text "(.GBS)" at 11876.44,6634.06 h41
  text "Solder Resist" at 13078.4,6634.06 h41
M13 Component Bodies Top:
  text ".Layer_Name" at 77,-1358.49 h60
M14 Component Bodies Bottom:
  text ".Layer_Name" at 77,-1358.49 h60
M15 Courtyards Top:
  text ".Layer_Name" at 77,-1358.49 h60
M16 Courtyards Bottom:
  text ".Layer_Name" at 77,-1358.49 h60
Drill Drawing:
  text ".legend" at 2330,685 h60
  text "Drill Table" at 2340,570 h60
  text "FOR 16MIL DRILL +0/-16MIL" at 2345,459 h60
  text "FOR PTH DRILL +/-3MIL" at 2350,360 h60
  text "FOR NPTH DRILL +/-2MIL" at 2350,265 h60
  text ".Layer_Name" at 77,-1358.49 h60

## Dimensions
0,0 to 2000,0 on Drill Drawing
0,0 to 0,2000 on Drill Drawing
